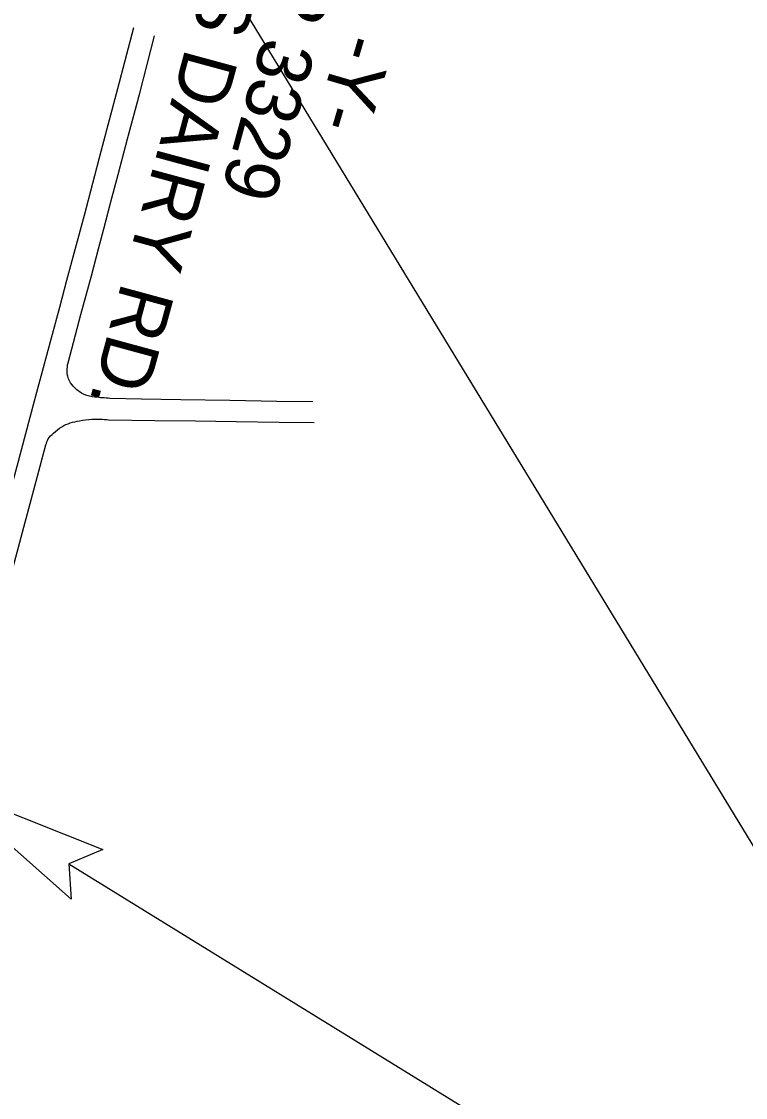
# Model space of a CAD drawing. Extents: x 1771071 to 1790027, y 804210 to 823391.
# Drawn here: x 1783081 to 1783735, y 815031 to 816004 of the extents above; entities that cross this region are included whole.
import ezdxf

# ---------------------------------------------------------------- set-up
doc = ezdxf.new("R2010")
doc.units = 0
for name, color, linetype in [('Exist Roads EOP', 7, 'Continuous'), ('Prop CMT Guardrail Graphics', 7, 'Continuous'), ('Prop Conc Shoulder Berm Gutter', 7, 'Continuous'), ('Prop Horizontal Alignment', 7, 'Continuous'), ('Prop Superelevation Label', 7, 'Continuous'), ('Scratch_Level_7', 7, 'Continuous')]:
    doc.layers.add(name, color=color, linetype=linetype)

msp = doc.modelspace()

# ---------------------------------------------------------------- linework, layer by layer
at = {"layer": 'Exist Roads EOP'}
for points in [[(1782983.08, 815250.42), (1782997.87, 815306.06), (1783014.55, 815368.48), (1783029.99, 815425.98), (1783044.8, 815481.13), (1783061.8, 815544.76), (1783077.09, 815601.83), (1783092.82, 815660.85), (1783108.2, 815717.8), (1783115.67, 815745.77), (1783122.14, 815769.94), (1783138.05, 815829.01), (1783153.26, 815886.72), (1783168.1, 815943.43), (1783182.63, 815998.55)], [(1783123.16, 815695.38), (1783134.7, 815739.15), (1783144.31, 815774.1), (1783150.58, 815798.45), (1783155.4, 815816.44), (1783161.95, 815841.02), (1783168.52, 815865.56), (1783177.03, 815897.92), (1783188.1, 815939.32), (1783201.47, 815991.15)], [(1783344.43, 815660.08), (1783312.03, 815660.46), (1783269.5, 815661.34), (1783225.2, 815661.88), (1783189.44, 815662.49), (1783161.01, 815663.21)], [(1783159.9, 815643.89), (1783201.49, 815643.25), (1783238.47, 815642.81), (1783275.08, 815642.32), (1783313.94, 815641.78), (1783345.6, 815641.41)], [(1783009.61, 815271.62), (1783016.48, 815296.9), (1783027.5, 815338.76), (1783039.98, 815385.98), (1783052.19, 815431.56), (1783063.75, 815474.24), (1783071.06, 815501.47), (1783083.34, 815546.57), (1783095.6, 815592.71), (1783103.23, 815621.01)]]:
    msp.add_lwpolyline(points, dxfattribs=at)
for points in [[(1783161.01, 815663.21), (1783147.51, 815664.33), (1783137.73, 815666.63), (1783129.29, 815672.78), (1783124.57, 815678.9), (1783122.35, 815687.73), (1783123.16, 815695.38)], [(1783103.23, 815621.01), (1783105.12, 815626.44), (1783110.12, 815631.76), (1783117.55, 815637.54), (1783125.16, 815640.95), (1783133.45, 815642.9), (1783144.68, 815644.33), (1783159.9, 815643.89)]]:
    msp.add_spline(points, degree=3, dxfattribs=at)
at = {"layer": 'Prop CMT Guardrail Graphics'}
msp.add_lwpolyline([(1779933.99, 817128.99), (1779440.87, 817677.57), (1777767.1, 816648.43), (1779807.57, 813286.94), (1778788.36, 812657.13), (1781190.7, 808756.53), (1783067.61, 810931.33), (1784924.9, 813315.98), (1781884.46, 818311.42)], close=True, dxfattribs=at)
at = {"layer": 'Prop Conc Shoulder Berm Gutter'}
msp.add_line((1783123.93, 815242.35), (1783709.19, 814881.11), dxfattribs=at)
at = {"layer": 'Prop Superelevation Label'}
msp.add_lwpolyline([(1783125.99, 815210.34), (1783010.48, 815312.37), (1783154.62, 815255.13), (1783123.93, 815242.35)], close=True, dxfattribs=at)

# ---------------------------------------------------------------- texts
at = {"layer": 'Prop Horizontal Alignment'}
msp.add_text('R-2612B SURVEY CONTROL SHEET', height=208.6956, rotation=301.42495, dxfattribs=at).set_placement((1783566.11, 819062.77))
at = {"layer": 'Scratch_Level_7'}
for s, height, rotation, p in [('WILLIAMS DAIRY RD.', 49.2075, 254.77838, (1783317.01, 816302.21)), ('SR 3329', 49.208, 254.77838, (1783328.49, 816097.32)), ('-Y-', 49.208, 253.61363, (1783370.63, 815995.95))]:
    msp.add_text(s, height=height, rotation=rotation, dxfattribs=at).set_placement(p)

doc.saveas('drawing.dxf')
